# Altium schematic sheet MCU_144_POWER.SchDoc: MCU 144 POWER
size A4; Date: Not used; ApprovedBy: Not used; CheckedBy: Not used; Author: Not used; CompanyName: STMicroelectronics; DrawnBy: Not used; Engineer: Not used; Organization: Not used; Address1: Not used; Address2: Not used; Address3: Not used; Address4: Not used; DocumentNumber: 4; Revision: Not used; SheetNumber: 4; SheetTotal: 9
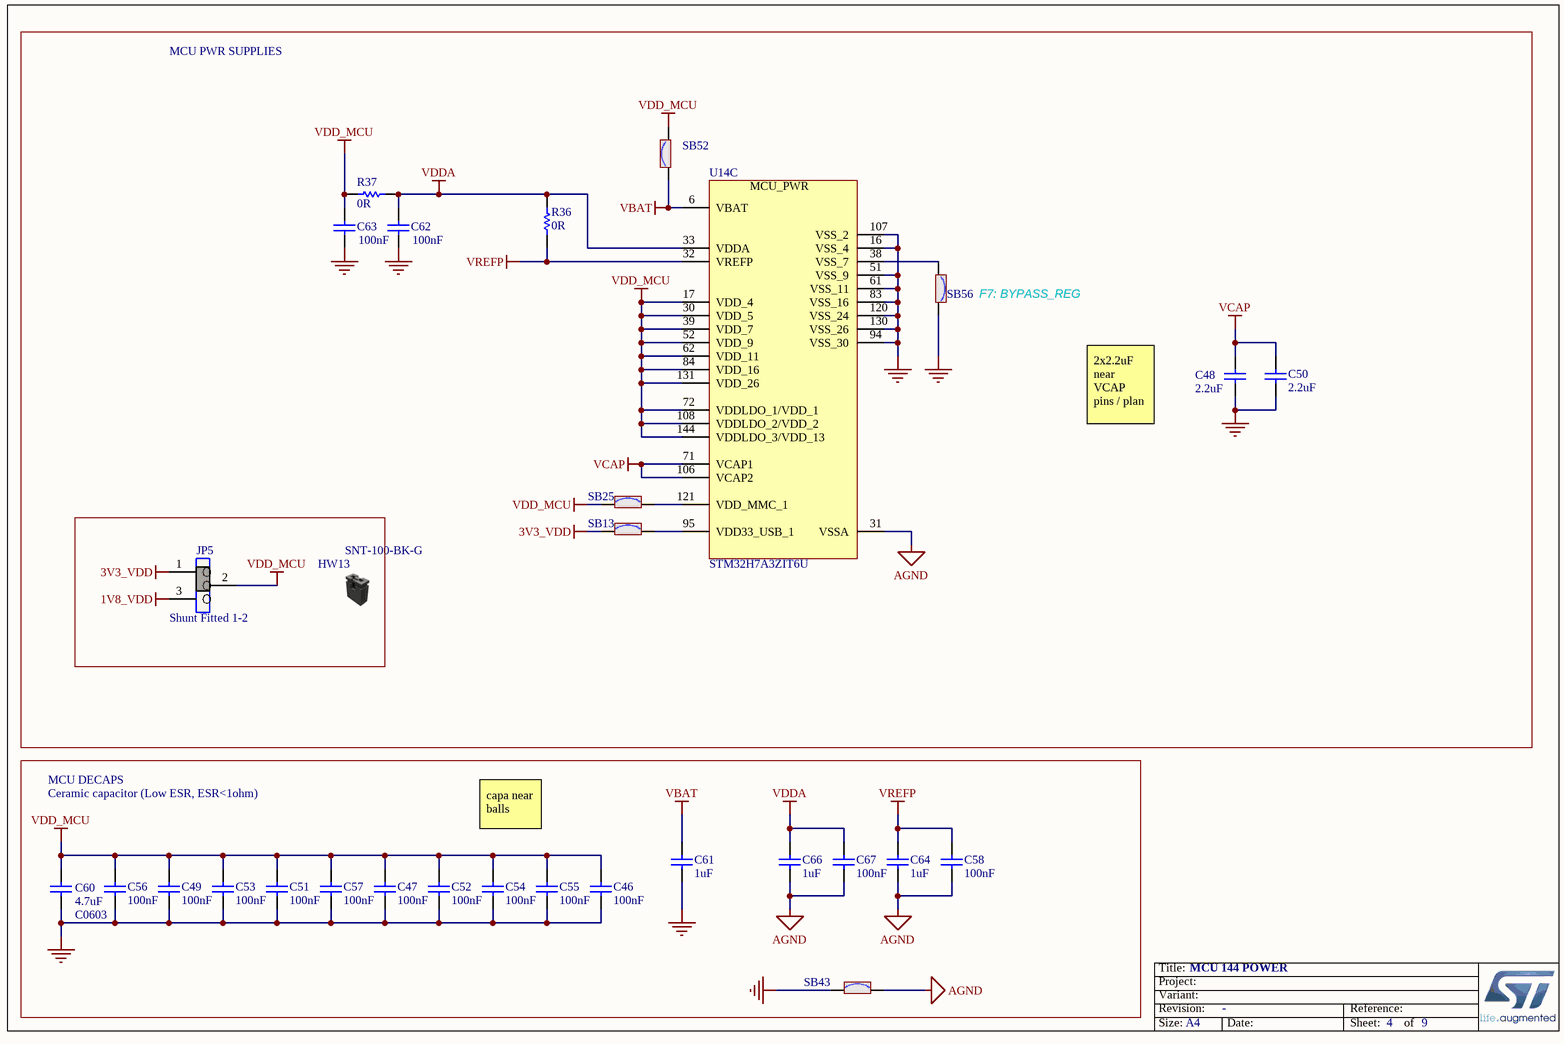
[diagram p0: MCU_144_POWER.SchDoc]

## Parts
C46  value 100nF  [C0402]  (hidden comment: Capacitor)
C47  value 100nF  [C0402]  (hidden comment: Capacitor)
C48  value 2.2uF  [C0603]  (hidden comment: Capacitor)
C49  value 100nF  [C0402]  (hidden comment: Capacitor)
C50  value 2.2uF  [C0603]  (hidden comment: Capacitor)
C51  value 100nF  [C0402]  (hidden comment: Capacitor)
C52  value 100nF  [C0402]  (hidden comment: Capacitor)
C53  value 100nF  [C0402]  (hidden comment: Capacitor)
C54  value 100nF  [C0402]  (hidden comment: Capacitor)
C55  value 100nF  [C0402]  (hidden comment: Capacitor)
C56  value 100nF  [C0402]  (hidden comment: Capacitor)
C57  value 100nF  [C0402]  (hidden comment: Capacitor)
C58  value 100nF  [C0402]  (hidden comment: Capacitor)
C60  value 4.7uF  [C0603]  (hidden comment: Capacitor)
C61  value 1uF  [C0603]  (hidden comment: Capacitor)
C62  value 100nF  [C0402]  (hidden comment: Capacitor)
C63  value 100nF  [C0402]  (hidden comment: Capacitor)
C64  value 1uF  [C0603]  (hidden comment: Capacitor)
C66  value 1uF  [C0603]  (hidden comment: Capacitor)
C67  value 100nF  [C0402]  (hidden comment: Capacitor)
HW13  value SNT-100-BK-G  (hidden comment: Shunt Black 2.54mm)  (mechanical)
JP5  value Shunt Fitted 1-2  [CON_SAMTEC_TSW-103-07-F-S]  (hidden comment: Jumper_Header 3x1 Fitted 1-2)
R36  value 0R  [R0603]  (hidden comment: Resistor)
R37  value 0R  [R0603]  (hidden comment: Resistor)
SB13  SB_ON  [SOLDER-BRIDGE_R0603-0R]  (value not drawn)
SB25  SB_ON  [SOLDER-BRIDGE_R0603-0R]  (value not drawn)
SB43  SB_ON  [SOLDER-BRIDGE_R0603-0R]  (value not drawn)
SB52  SB_ON  [SOLDER-BRIDGE_R0603-0R]  (value not drawn)
SB56  SB_ON  [SOLDER-BRIDGE_R0603-0R]  (value not drawn)
U14  value STM32H7A3ZIT6U  [ICC_LQFP144_20X20_P050_SOCKET_YAMAICHI_IC149-144-145-B5_NM]  (hidden comment: STM32H7A3ZIT6)  (part C of 3)

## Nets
1V8_VDD: JP5.3
3V3_VDD: JP5.1 SB13.1
AGND: C58.1 C64.2 C66.2 C67.1 SB43.2 U14.31(VSSA)
GND: C46.1 C47.1 C48.1 C49.1 C50.1 C51.1 C52.1 C53.1 C54.1 C55.1 C56.1 C57.1 C60.1 C61.1 C62.2 C63.2 SB43.1 SB56.2 U14.16(VSS_4) U14.51(VSS_9) U14.61(VSS_11) U14.83(VSS_16) U14.94(VSS_30) U14.107(VSS_2) U14.120(VSS_24) U14.130(VSS_26)
VBAT: C61.2 SB52.1 U14.6(VBAT)
VCAP: C48.2 C50.2 U14.71(VCAP1) U14.106(VCAP2)
VDD_MCU: C46.2 C47.2 C49.2 C51.2 C52.2 C53.2 C54.2 C55.2 C56.2 C57.2 C60.2 C63.1 JP5.2 R37.1 SB25.1 SB52.2 U14.17(VDD_4) U14.30(VDD_5) U14.39(VDD_7) U14.52(VDD_9) U14.62(VDD_11) U14.72(VDDLDO_1/VDD_1) U14.84(VDD_16) U14.108(VDDLDO_2/VDD_2) U14.131(VDD_26) U14.144(VDDLDO_3/VDD_13)
VDDA: C62.1 C66.1 C67.2 R36.1 R37.2 U14.33(VDDA)
VREFP: C58.2 C64.1 R36.2 U14.32(VREFP)
NetSB13_2: SB13.2 U14.95(VDD33_USB_1)
NetSB25_2: SB25.2 U14.121(VDD_MMC_1)
NetSB56_1: SB56.1 U14.38(VSS_7)

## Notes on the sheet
- MCU PWR SUPPLIES
- (near SB56) F7: BYPASS_REG
- 2x2.2uF near VCAP pins / plan
- MCU DECAPS
- Ceramic capacitor (Low ESR, ESR<1ohm)
- capa near balls

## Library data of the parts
C46 C47 C49 C51-C58 C67 = MCD-01123: [obsolete] Capacitor, MLCC,100nF, 10V, X7R, 10%, 0402, T=0.5mm; Manufacturer_Part_Number: NRND_GRM155R71A104KA01; Manufacturer: MURATA; Provided_By: SUBCO; ECCN_US: EAR99; ECCN_EU: NEC
C48 C50 = MCD-00012: Capacitor, MLCC, 2.2uF, 10V, X5R, 10%, 0603, T=0,8mm; Manufacturer_Part_Number: CC0603KRX5R6BB225; Manufacturer: YAGEO; Alternate_Manufacturer_Part_Number: C0603C225K8PACTU; Alternate_Manufacturer: KEMET; Provided_By: SUBCO; ECCN_US: EAR99; ECCN_EU: NEC
C60 = MCD-01121: Capacitor, MLCC, 4.7µF, 10V, X5R, 20%, 0603, T=0,8mm; Manufacturer_Part_Number: GRM188R61A475ME15; Manufacturer: MURATA; Provided_By: SUBCO; ECCN_US: EAR99; ECCN_EU: NEC
C61 C64 C66 = MCD-00238: Capacitor, MLCC, 1uF, 6V3, X5R, 10%, 0603, T=0,8mm; Manufacturer_Part_Number: CC0603KRX5R5BB105; Manufacturer: YAGEO; Provided_By: SUBCO; ECCN_US: EAR99; ECCN_EU: NEC
C62 C63 = MCD-00006: Capacitor, MLCC, 100nF, 16V, X7R, 10%, 0402, T=0.5mm; Manufacturer_Part_Number: CC0402KRX7R7BB104; Manufacturer: YAGEO; Alternate_Manufacturer_Part_Number: GCM155R71C104KA55D; Alternate_Manufacturer: MURATA; Provided_By: SUBCO; ECCN_US: EAR99; ECCN_EU: NEC
HW13 = MCD-00043: SHUNT 2.54mm BLACK; Manufacturer: SAMTEC; Part_Type: Mechanical; Alternate_Manufacturer_Part_Number: 316102S111A; Alternate_Manufacturer: JIUBABA; Provided_By: SUBCO
JP5 = MCD-00684: Header, 3x1, 2,54mm, VR, TH, Height 5.84mm/2.54mm - Shunt Fitted 1-2 by default; Part_Type: Connector; Manufacturer_Part_Number: TSW-103-07-F-S; Manufacturer: SAMTEC; Provided_By: SUBCO
R36 R37 = MCD-00056: Resistor,0R,0603,5%,1/10W; Manufacturer_Part_Number: RC0603JR-070RL; Manufacturer: YAGEO; Provided_By: SUBCO; ECCN_US: EAR99; ECCN_EU: NEC
SB13 SB25 SB43 SB52 SB56 = MCD-00071: Solder Bridge ON; Part_Type: Mechanical; Manufacturer_Part_Number: RC0603JR-070RL; Manufacturer: YAGEO; Provided_By: SUBCO
U14 = MCD-01349: STM32H7A3ZIT6U, LQFP144 package, 20x20; Part_Type: IC; Manufacturer: STMICROELECTRONICS; BMS_Part_Number: 9175347; Provided_By: SUBCO with ST control; ECCN_US: 3A991A2; ECCN_EU: NEC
